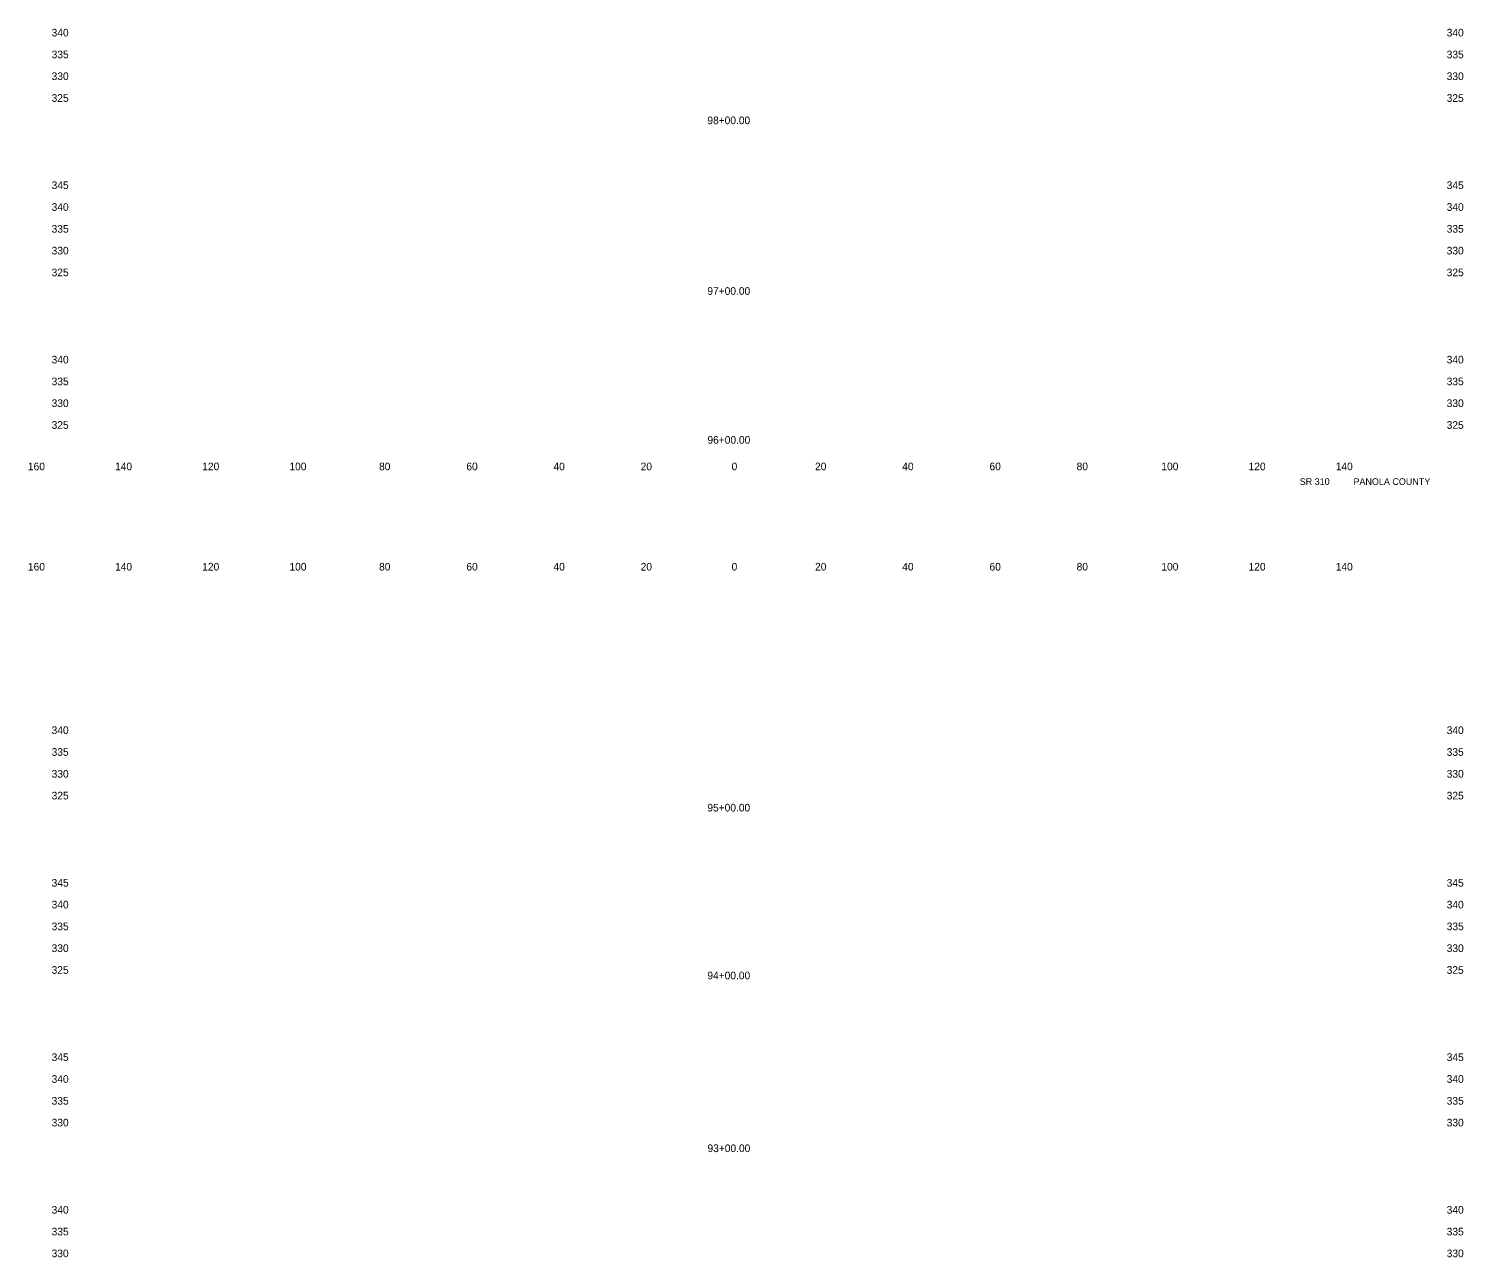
# Model space of a CAD drawing. Extents: x 21481 to 21810, y 6485 to 11067.
# Drawn here: x 21480.9 to 21809.9, y 6767.7 to 7049.5 of the extents above; entities that cross this region are included whole.
import ezdxf

# ---------------------------------------------------------------- set-up
doc = ezdxf.new("R2010")
doc.units = 0
for name, color, linetype in [('62', 7, 'Continuous'), ('XS_CELL', 7, 'Continuous'), ('XS_P_TX_DCH', 7, 'Continuous'), ('XS_P_TX_FS_BS', 7, 'Continuous')]:
    doc.layers.add(name, color=color, linetype=linetype)

msp = doc.modelspace()

# ---------------------------------------------------------------- texts
at = {"layer": '62'}
for s, p in [('  160  ', (21479.4, 6948.21)), ('  140  ', (21499.39, 6948.21)), ('  120  ', (21519.39, 6948.21)), ('  100  ', (21539.39, 6948.21)), ('  80  ', (21559.95, 6948.21)), ('  60  ', (21579.97, 6948.21)), ('  40  ', (21599.95, 6948.21)), ('  20  ', (21619.95, 6948.21)), ('  0  ', (21640.81, 6948.21)), ('  0  ', (21640.81, 6948.21)), ('  20  ', (21659.95, 6948.21)), ('  40  ', (21679.95, 6948.21)), ('  60  ', (21699.97, 6948.21)), ('  80  ', (21719.95, 6948.21)), ('  100  ', (21739.39, 6948.21)), ('  120  ', (21759.39, 6948.21)), ('  140  ', (21779.39, 6948.21)), ('  160  ', (21479.4, 6925.21)), ('  140  ', (21499.39, 6925.21)), ('  120  ', (21519.39, 6925.21)), ('  100  ', (21539.39, 6925.21)), ('  80  ', (21559.95, 6925.21)), ('  60  ', (21579.97, 6925.21)), ('  40  ', (21599.95, 6925.21)), ('  20  ', (21619.95, 6925.21)), ('  0  ', (21640.81, 6925.21)), ('  0  ', (21640.81, 6925.21)), ('  20  ', (21659.95, 6925.21)), ('  40  ', (21679.95, 6925.21)), ('  60  ', (21699.97, 6925.21)), ('  80  ', (21719.95, 6925.21)), ('  100  ', (21739.39, 6925.21)), ('  120  ', (21759.39, 6925.21)), ('  140  ', (21779.39, 6925.21))]:
    msp.add_text(s, height=1.75, dxfattribs=at).set_placement(p)
at = {"layer": 'XS_CELL'}
for s, p in [('  340  ', (21484.84, 7047.71)), ('  340  ', (21804.84, 7047.71)), ('  335  ', (21484.84, 7042.71)), ('  335  ', (21804.84, 7042.71)), ('  330  ', (21484.84, 7037.71)), ('  330  ', (21804.84, 7037.71)), ('  325  ', (21484.84, 7032.71)), ('  325  ', (21804.84, 7032.71)), ('  345  ', (21484.84, 7012.71)), ('  345  ', (21804.84, 7012.71)), ('  340  ', (21484.84, 7007.71)), ('  340  ', (21804.84, 7007.71)), ('  335  ', (21484.84, 7002.71)), ('  335  ', (21804.84, 7002.71)), ('  330  ', (21484.84, 6997.71)), ('  330  ', (21804.84, 6997.71)), ('  325  ', (21484.84, 6992.71)), ('  325  ', (21804.84, 6992.71)), ('  340  ', (21484.84, 6972.71)), ('  340  ', (21804.84, 6972.71)), ('  335  ', (21484.84, 6967.71)), ('  335  ', (21804.84, 6967.71)), ('  330  ', (21484.84, 6962.71)), ('  330  ', (21804.84, 6962.71)), ('  325  ', (21484.84, 6957.71)), ('  325  ', (21804.84, 6957.71)), ('  340  ', (21484.84, 6887.71)), ('  340  ', (21804.84, 6887.71)), ('  335  ', (21484.84, 6882.71)), ('  335  ', (21804.84, 6882.71)), ('  330  ', (21484.84, 6877.71)), ('  330  ', (21804.84, 6877.71)), ('  325  ', (21484.84, 6872.71)), ('  325  ', (21804.84, 6872.71)), ('  345  ', (21484.84, 6852.71)), ('  345  ', (21804.84, 6852.71)), ('  340  ', (21484.84, 6847.71)), ('  340  ', (21804.84, 6847.71)), ('  335  ', (21484.84, 6842.71)), ('  335  ', (21804.84, 6842.71)), ('  330  ', (21484.84, 6837.71)), ('  330  ', (21804.84, 6837.71)), ('  325  ', (21484.84, 6832.71)), ('  325  ', (21804.84, 6832.71)), ('  345  ', (21484.84, 6812.71)), ('  345  ', (21804.84, 6812.71)), ('  340  ', (21484.84, 6807.71)), ('  340  ', (21804.84, 6807.71)), ('  335  ', (21484.84, 6802.71)), ('  335  ', (21804.84, 6802.71)), ('  330  ', (21484.84, 6797.71)), ('  330  ', (21804.84, 6797.71)), ('  340  ', (21484.84, 6777.71)), ('  340  ', (21804.84, 6777.71)), ('  335  ', (21484.84, 6772.71)), ('  335  ', (21804.84, 6772.71)), ('  330  ', (21484.84, 6767.71)), ('  330  ', (21804.84, 6767.71))]:
    msp.add_text(s, height=1.75, dxfattribs=at).set_placement(p)
at = {"layer": 'XS_P_TX_DCH'}
for s, p in [('  98+00.00  ', (21635.25, 7027.59)), ('  97+00.00  ', (21635.25, 6988.45)), ('  96+00.00  ', (21635.27, 6954.3)), ('  95+00.00  ', (21635.25, 6869.94)), ('  94+00.00  ', (21635.25, 6831.45)), ('  93+00.00  ', (21635.28, 6791.82))]:
    msp.add_text(s, height=1.75, dxfattribs=at).set_placement(p)
at = {"layer": 'XS_P_TX_FS_BS'}
for s, p in [('SR 310', (21772.43, 6944.84)), ('SR 310', (21772.43, 6944.84)), ('SR 310', (21772.43, 6944.84)), ('PANOLA COUNTY', (21784.75, 6944.84)), ('PANOLA COUNTY', (21784.75, 6944.84)), ('PANOLA COUNTY', (21784.75, 6944.84))]:
    msp.add_text(s, height=1.54, dxfattribs=at).set_placement(p)

doc.saveas('drawing.dxf')
